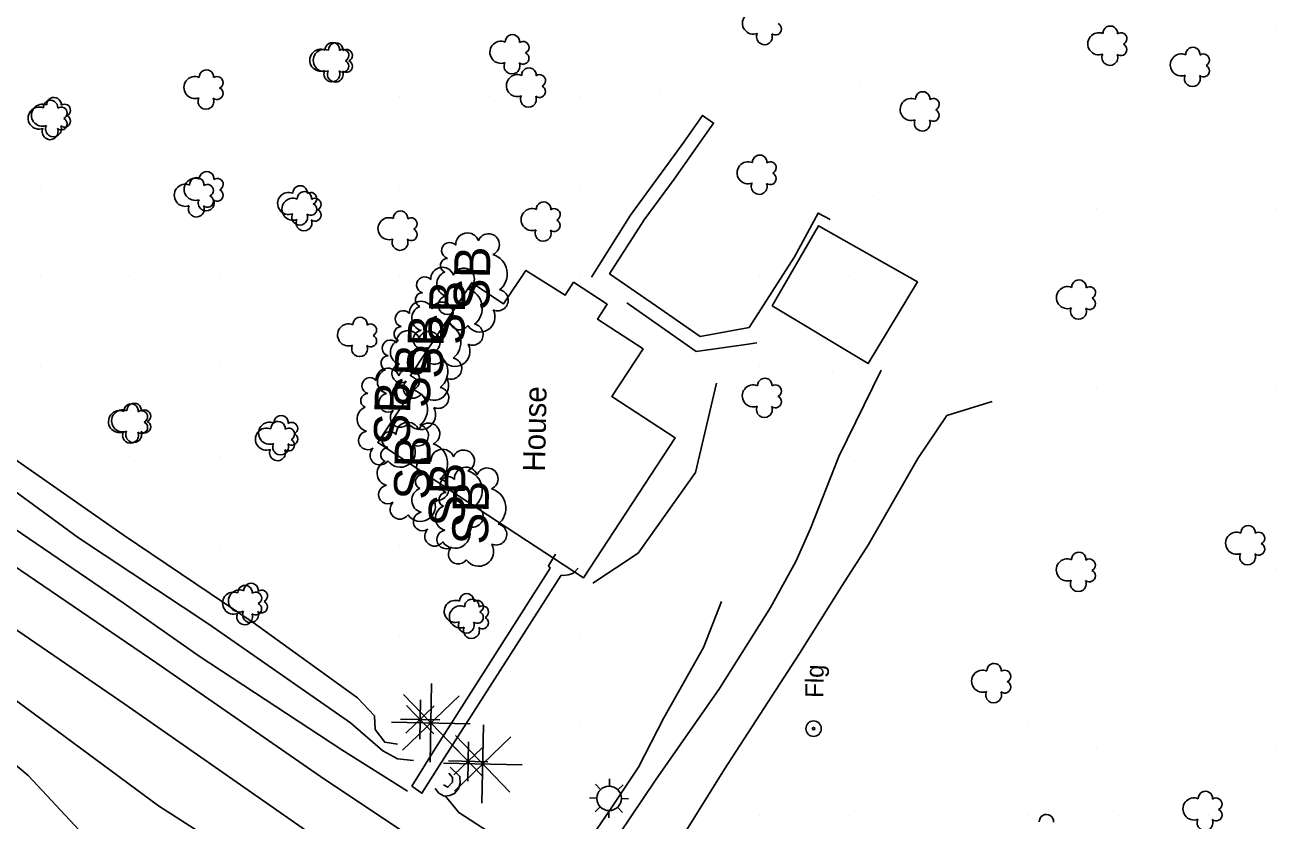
# Model space of a CAD drawing. Extents: x 19528164 to 19545171, y 7585743 to 7602745.
# Drawn here: x 19535061.7 to 19535340, y 7588133.8 to 7588310.9 of the extents above; entities that cross this region are included whole.
import ezdxf

# ---------------------------------------------------------------- set-up
doc = ezdxf.new("R2010")
doc.units = 0
for name, color, linetype in [('Default', 7, 'Continuous'), ('PhoBreakLine', 7, 'Continuous'), ('PhoBuilding', 7, 'Continuous'), ('PhoDrainageArrow', 7, 'Continuous'), ('PhoEdgeRoadPaved', 7, 'Continuous'), ('PhoEdgeSidewalk', 7, 'Continuous'), ('PhoISAEPoints', 7, 'Continuous'), ('PhoNotesDesign', 7, 'Continuous'), ('PhoVegetation', 7, 'Continuous'), ('SurAlignment', 7, 'Continuous'), ('SurEdgeEntranceUnpaved', 7, 'Continuous'), ('SurNaturalCells', 7, 'Continuous'), ('SurROWRail', 7, 'Continuous')]:
    doc.layers.add(name, color=color, linetype=linetype)

# ---------------------------------------------------------------- blocks, each defined once
blk = doc.blocks.new('SHRUB')
at = {"layer": 'Default'}
for centre, radius, start, end in [((-5.57, 5.14), 2.08, 10.5948, 214.3611), ((-0.81, 4.83), 2.81, 22.6036, 165.7836), ((3.27, 5.33), 1.59, 0.4605, 158.7839), ((6.61, 4.92), 1.8, 311.3936, 166.4114), ((-8.82, 2.41), 2.18, 45.3455, 236.8073), ((8, 0.98), 2.6, 290.9039, 94.3687), ((-8.06, -2.12), 3.34, 125.8289, 299.2848), ((8.09, -3.71), 2.42, 204.8294, 69.8871), ((-4.25, -5.95), 2.36, 157.0258, 349.7602), ((1.54, -3.45), 4.54, 220.0183, 343.6977)]:
    blk.add_arc(centre, radius, start, end, dxfattribs=at)
blk.add_text('SB', height=7.998, dxfattribs=at).set_placement((-6.62, -4.17))
blk = doc.blocks.new('TREV')
at = {"layer": 'Default'}
for p, q in [((0, -8.75), (0, 8.75)), ((-6.18, -6.19), (6.19, 6.18)), ((6.18, -6.18), (-6.18, 6.18)), ((-8.75, 0), (8.75, 0)), ((0, 0), (0, 0))]:
    blk.add_line(p, q, dxfattribs=at)
blk = doc.blocks.new('TRDC')
at = {"layer": 'PhoVegetation'}
for centre, radius, start, end in [((0.07, 3.96), 4.92, 338.2051, 201.7949), ((-5.96, -1.07), 3.52, 65.4824, 294.5175), ((4.86, -1.07), 3.21, 265.9982, 94.0018), ((-2.37, -5.89), 2.68, 142.7501, 335.3223), ((2.46, -5.82), 2.67, 206.5242, 35.4033)]:
    blk.add_arc(centre, radius, start, end, dxfattribs=at)

msp = doc.modelspace()

# ---------------------------------------------------------------- linework, layer by layer
at = {"layer": 'PhoBreakLine'}
for points in [[(19535324.95, 7587995.18), (19535295, 7588014.27), (19535258.67, 7588039.68), (19535219.66, 7588066.35), (19535185.84, 7588090.28), (19535159.88, 7588107.73), (19535126.48, 7588130.01), (19535083.85, 7588159.79), (19535046.8, 7588185.14), (19535011.18, 7588210.1), (19534967.03, 7588240.29), (19534940.46, 7588257.57), (19534928.49, 7588265.98)], [(19534985.67, 7588263.96), (19534982.83, 7588261.36), (19534981.42, 7588258.72), (19534981.19, 7588254.56), (19534982.64, 7588251.54), (19534993.07, 7588244.02), (19535010.16, 7588233.52), (19535035.49, 7588216.1), (19535057.59, 7588199.98), (19535083.47, 7588182.34), (19535100.37, 7588170.43), (19535132.13, 7588149.63), (19535146.75, 7588140.38)], [(19534986.82, 7588262.88), (19534998.99, 7588255.22), (19535016.97, 7588243.81), (19535047.5, 7588222.53), (19535083.52, 7588197.42), (19535112.43, 7588177.92), (19535135.63, 7588161.21), (19535139.45, 7588157.16), (19535139.53, 7588154.1), (19535141.69, 7588151.29), (19535141.69, 7588151.29), (19535144.57, 7588150.83)], [(19535188.01, 7588186.7), (19535198.11, 7588193.4), (19535210.84, 7588211.34), (19535215.51, 7588231.24), (19535215.51, 7588231.24)], [(19535155.11, 7588139.33), (19535158.2, 7588135.66), (19535164.68, 7588131.41), (19535170.22, 7588128.02), (19535174.93, 7588126.48), (19535178.73, 7588126.21), (19535184.36, 7588127.72), (19535188.08, 7588130.74), (19535191.65, 7588135.96), (19535198.13, 7588145.76), (19535203.79, 7588156.69), (19535212.61, 7588172.38), (19535216.59, 7588182.6)], [(19535032.29, 7588166.67), (19535046.33, 7588157.29), (19535062.39, 7588143.85), (19535074.76, 7588130.6), (19535080.78, 7588122.57), (19535094.85, 7588112.32), (19535102.21, 7588105.88), (19535125.38, 7588091.61), (19535137.29, 7588084.91)], [(19535152.88, 7588141.02), (19535153.76, 7588139.97), (19535154.91, 7588139.3), (19535156.17, 7588139.46), (19535157.24, 7588139.91), (19535158.12, 7588141.02), (19535158.49, 7588142.16), (19535158.42, 7588143.68), (19535156.29, 7588145.73)], [(19535154.74, 7588141.81), (19535155.75, 7588141.28), (19535156.78, 7588142.43), (19535156.8, 7588143.41), (19535155.98, 7588144.44)]]:
    msp.add_lwpolyline(points, dxfattribs=at)
at = {"layer": 'PhoBuilding'}
for points in [[(19535227.93, 7588248.4), (19535249.24, 7588235.56), (19535260.23, 7588253.74), (19535238.21, 7588266.25)], [(19535162.45, 7588203.27), (19535185.95, 7588187.89), (19535206.32, 7588219.03), (19535192.24, 7588228.23), (19535199.18, 7588238.85), (19535189.06, 7588245.46), (19535191.22, 7588248.79), (19535183.7, 7588253.67), (19535181.81, 7588250.79), (19535173.12, 7588256.31), (19535168.15, 7588248.89), (19535161.05, 7588253.57), (19535147.41, 7588232.9), (19535149.2, 7588231.73), (19535140.13, 7588217.99)], [(19535162.45, 7588203.27), (19535185.95, 7588187.89), (19535206.32, 7588219.03), (19535192.24, 7588228.23), (19535199.18, 7588238.85), (19535189.06, 7588245.46), (19535191.22, 7588248.79), (19535183.7, 7588253.67), (19535181.81, 7588250.79), (19535173.12, 7588256.31), (19535168.15, 7588248.89), (19535161.05, 7588253.57), (19535147.41, 7588232.9), (19535149.2, 7588231.73), (19535140.13, 7588217.99)]]:
    msp.add_lwpolyline(points, close=True, dxfattribs=at)
at = {"layer": 'PhoDrainageArrow'}
msp.add_lwpolyline([(19534985.15, 7588257.93), (19534991.63, 7588254.76), (19535003.26, 7588245.82), (19535023.92, 7588232.81), (19535050.41, 7588213.74), (19535073.55, 7588196.77), (19535102.55, 7588177.54), (19535134.09, 7588155.62), (19535141.25, 7588149.38), (19535144.56, 7588147.6), (19535148.09, 7588147.22)], dxfattribs=at)
at = {"layer": 'PhoEdgeRoadPaved'}
msp.add_lwpolyline([(19535057.27, 7588191.87), (19535090.95, 7588168.89), (19535090.97, 7588168.89), (19535127.4, 7588143.65), (19535166.06, 7588117.85), (19535239.5, 7588067.23), (19535269.12, 7588046.94), (19535311.25, 7588018.15), (19535329.73, 7588005.02), (19535324.75, 7587994.76), (19535318.21, 7587985.66), (19535298.76, 7587998.91), (19535278.77, 7588012.97), (19535253.58, 7588029.66), (19535223.79, 7588049.16), (19535206.77, 7588060.17), (19535179.37, 7588080), (19535153.78, 7588097.51), (19535135.89, 7588108.59), (19535091.35, 7588137.16), (19535042.62, 7588173.1)], dxfattribs=at)
at = {"layer": 'PhoEdgeSidewalk'}
for points in [[(19535187.68, 7588254.79), (19535196.37, 7588268.6), (19535208.24, 7588284.88), (19535212.37, 7588290.81), (19535214.85, 7588289.11), (19535206.09, 7588276.6), (19535199.44, 7588267.58), (19535191.72, 7588255.56), (19535202.13, 7588248.39), (19535211.89, 7588241.57), (19535222.75, 7588243.59), (19535232.84, 7588259.34), (19535238.13, 7588269.06), (19535240.83, 7588267.62)], [(19535195.56, 7588249.09), (19535210.98, 7588238.3), (19535222.02, 7588239.86), (19535224.5, 7588240.21)], [(19535178.53, 7588190.02), (19535178.12, 7588190.59), (19535179.67, 7588193.12)], [(19535147.69, 7588141.49), (19535152.47, 7588149.16), (19535178.53, 7588190.02)], [(19535180.92, 7588188.49), (19535181.53, 7588188.44), (19535182.49, 7588188.54), (19535183.32, 7588188.8), (19535183.78, 7588189.02), (19535184.77, 7588190.07)], [(19535147.69, 7588141.49), (19535149.95, 7588139.94), (19535153.83, 7588146.01), (19535180.92, 7588188.49)]]:
    msp.add_lwpolyline(points, dxfattribs=at)
at = {"layer": 'PhoISAEPoints'}
for p, q in [((19535081.56, 7588296.2), (19535081.56, 7588296.2)), ((19535065, 7588295), (19535065, 7588295)), ((19535105, 7588295), (19535105, 7588295)), ((19535125, 7588295), (19535125, 7588295)), ((19535145, 7588295), (19535145, 7588295)), ((19535165, 7588295), (19535165, 7588295)), ((19535065, 7588275), (19535065, 7588275)), ((19535085, 7588275), (19535085, 7588275)), ((19535105, 7588275), (19535105, 7588275)), ((19535125, 7588275), (19535125, 7588275)), ((19535145, 7588275), (19535145, 7588275)), ((19535165, 7588275), (19535165, 7588275)), ((19535165.65, 7588259.21), (19535165.65, 7588259.21)), ((19535065, 7588255), (19535065, 7588255)), ((19535085, 7588255), (19535085, 7588255)), ((19535085, 7588255), (19535085, 7588255)), ((19535105, 7588255), (19535105, 7588255)), ((19535125, 7588255), (19535125, 7588255)), ((19535145, 7588255), (19535145, 7588255)), ((19535065, 7588235), (19535065, 7588235)), ((19535085, 7588235), (19535085, 7588235)), ((19535105, 7588235), (19535105, 7588235)), ((19535125, 7588235), (19535125, 7588235)), ((19535142.55, 7588233.67), (19535142.55, 7588233.67)), ((19535076.26, 7588224.98), (19535076.26, 7588224.98)), ((19535085.12, 7588225.18), (19535085.12, 7588225.18)), ((19535085, 7588215), (19535085, 7588215)), ((19535105, 7588215), (19535105, 7588215)), ((19535125, 7588215), (19535125, 7588215)), ((19535142.12, 7588212.73), (19535142.12, 7588212.73)), ((19535105, 7588195), (19535105, 7588195)), ((19535125, 7588195), (19535125, 7588195)), ((19535145, 7588195), (19535145, 7588195)), ((19535145, 7588195), (19535145, 7588195)), ((19535165, 7588195), (19535165, 7588195)), ((19535205, 7588195), (19535205, 7588195)), ((19535154.52, 7588186.52), (19535154.52, 7588186.52)), ((19535145, 7588175), (19535145, 7588175)), ((19535185, 7588175), (19535185, 7588175)), ((19535265, 7588175), (19535265, 7588175)), ((19535185, 7588155), (19535185, 7588155)), ((19535245, 7588155), (19535245, 7588155)), ((19535265, 7588155), (19535265, 7588155)), ((19535285, 7588155), (19535285, 7588155)), ((19535305, 7588155), (19535305, 7588155)), ((19535225, 7588135), (19535225, 7588135)), ((19535245, 7588135), (19535245, 7588135)), ((19535265, 7588135), (19535265, 7588135)), ((19535285, 7588135), (19535285, 7588135)), ((19535305, 7588135), (19535305, 7588135)), ((19535325, 7588135), (19535325, 7588135))]:
    msp.add_line(p, q, dxfattribs=at)
at = {"layer": 'PhoVegetation'}
for p, q in [((19535152.72, 7588159.36), (19535146.42, 7588153.29)), ((19535152.72, 7588159.36), (19535146.42, 7588153.29)), ((19535152.61, 7588153.18), (19535146.54, 7588159.48)), ((19535152.61, 7588153.18), (19535146.54, 7588159.48)), ((19535149.49, 7588151.95), (19535149.66, 7588160.7)), ((19535149.49, 7588151.95), (19535149.66, 7588160.7)), ((19535153.95, 7588156.24), (19535145.2, 7588156.41)), ((19535153.95, 7588156.24), (19535145.2, 7588156.41)), ((19535149.57, 7588156.33), (19535149.57, 7588156.33)), ((19535149.57, 7588156.33), (19535149.57, 7588156.33)), ((19535160.15, 7588142.66), (19535160.32, 7588151.41)), ((19535163.39, 7588150.07), (19535157.08, 7588144)), ((19535163.27, 7588143.88), (19535157.2, 7588150.19)), ((19535164.61, 7588146.95), (19535155.86, 7588147.12)), ((19535160.24, 7588147.04), (19535160.24, 7588147.04))]:
    msp.add_line(p, q, dxfattribs=at)
for centre, radius, start, end in [((19535223.73, 7588311.37), 2.46, 67.0981, 290.6879), ((19535228.63, 7588310.06), 1.34, 231.6431, 64.2153), ((19535303.13, 7588309.12), 1.6, 354.8912, 182.8948), ((19535130.81, 7588305.4), 1.6, 354.8912, 182.8948), ((19535167.55, 7588304.86), 2.46, 67.0981, 290.6879), ((19535170.11, 7588307.21), 1.6, 354.8912, 182.8948), ((19535172.46, 7588305.96), 1.34, 295.4172, 124.2963), ((19535226.18, 7588308.31), 1.76, 154.3754, 23.4105), ((19535300.57, 7588306.77), 2.46, 67.0981, 290.6879), ((19535305.48, 7588307.88), 1.34, 295.4172, 124.2963), ((19535128.25, 7588303.05), 2.46, 67.0981, 290.6879), ((19535133.16, 7588304.16), 1.34, 295.4172, 124.2963), ((19535172.45, 7588303.55), 1.34, 231.6431, 64.2153), ((19535303.03, 7588303.71), 1.76, 154.3754, 23.4105), ((19535305.47, 7588305.46), 1.34, 231.6431, 64.2153), ((19535318.95, 7588302.05), 2.46, 67.0981, 290.6879), ((19535321.51, 7588304.39), 1.6, 354.8912, 182.8948), ((19535323.86, 7588303.15), 1.34, 295.4172, 124.2963), ((19535133.15, 7588301.74), 1.34, 231.6431, 64.2153), ((19535170.01, 7588301.8), 1.76, 154.3754, 23.4105), ((19535173.78, 7588299.8), 1.6, 354.8912, 182.8948), ((19535323.85, 7588300.73), 1.34, 231.6431, 64.2153), ((19535099.47, 7588297.02), 2.46, 67.0981, 290.6879), ((19535102.03, 7588299.37), 1.6, 354.8912, 182.8948), ((19535104.38, 7588298.13), 1.34, 295.4172, 124.2963), ((19535130.7, 7588299.99), 1.76, 154.3754, 23.4105), ((19535171.22, 7588297.45), 2.46, 67.0981, 290.6879), ((19535176.13, 7588298.55), 1.34, 295.4172, 124.2963), ((19535321.4, 7588298.98), 1.76, 154.3754, 23.4105), ((19535104.37, 7588295.71), 1.34, 231.6431, 64.2153), ((19535176.12, 7588296.14), 1.34, 231.6431, 64.2153), ((19535261.39, 7588294.5), 1.6, 354.8912, 182.8948), ((19535067.34, 7588292.58), 1.6, 354.8912, 182.8948), ((19535101.92, 7588293.96), 1.76, 154.3754, 23.4105), ((19535173.67, 7588294.39), 1.76, 154.3754, 23.4105), ((19535258.84, 7588292.15), 2.46, 67.0981, 290.6879), ((19535263.74, 7588293.26), 1.34, 295.4172, 124.2963), ((19535064.79, 7588290.23), 2.46, 67.0981, 290.6879), ((19535069.69, 7588288.92), 1.34, 231.6431, 64.2153), ((19535069.69, 7588291.33), 1.34, 295.4172, 124.2963), ((19535263.73, 7588290.84), 1.34, 231.6431, 64.2153), ((19535067.24, 7588287.17), 1.76, 154.3754, 23.4105), ((19535261.29, 7588289.09), 1.76, 154.3754, 23.4105), ((19535225.12, 7588280.4), 1.6, 354.8912, 182.8948), ((19535222.56, 7588278.05), 2.46, 67.0981, 290.6879), ((19535227.47, 7588279.16), 1.34, 295.4172, 124.2963), ((19535099.88, 7588275.38), 1.6, 354.8912, 182.8948), ((19535227.46, 7588276.74), 1.34, 231.6431, 64.2153), ((19535097.32, 7588273.03), 2.46, 67.0981, 290.6879), ((19535102.23, 7588274.13), 1.34, 295.4172, 124.2963), ((19535123.84, 7588272.28), 1.6, 354.8912, 182.8948), ((19535225.01, 7588274.99), 1.76, 154.3754, 23.4105), ((19535099.78, 7588269.96), 1.76, 154.3754, 23.4105), ((19535102.22, 7588271.71), 1.34, 231.6431, 64.2153), ((19535121.28, 7588269.93), 2.46, 67.0981, 290.6879), ((19535126.19, 7588271.03), 1.34, 295.4172, 124.2963), ((19535177.05, 7588269.97), 1.6, 354.8912, 182.8948), ((19535126.18, 7588268.62), 1.34, 231.6431, 64.2153), ((19535142.65, 7588265.6), 2.46, 67.0981, 290.6879), ((19535145.21, 7588267.95), 1.6, 354.8912, 182.8948), ((19535147.56, 7588266.7), 1.34, 295.4172, 124.2963), ((19535174.49, 7588267.63), 2.46, 67.0981, 290.6879), ((19535179.4, 7588268.73), 1.34, 295.4172, 124.2963), ((19535123.74, 7588266.87), 1.76, 154.3754, 23.4105), ((19535147.55, 7588264.29), 1.34, 231.6431, 64.2153), ((19535176.95, 7588264.56), 1.76, 154.3754, 23.4105), ((19535179.39, 7588266.31), 1.34, 231.6431, 64.2153), ((19535145.1, 7588262.54), 1.76, 154.3754, 23.4105), ((19535296.16, 7588252.6), 1.6, 354.8912, 182.8948), ((19535293.61, 7588250.25), 2.46, 67.0981, 290.6879), ((19535298.52, 7588251.35), 1.34, 295.4172, 124.2963), ((19535298.51, 7588248.94), 1.34, 231.6431, 64.2153), ((19535136.2, 7588244.29), 1.6, 354.8912, 182.8948), ((19535296.06, 7588247.19), 1.76, 154.3754, 23.4105), ((19535133.65, 7588241.95), 2.46, 67.0981, 290.6879), ((19535138.55, 7588243.05), 1.34, 295.4172, 124.2963), ((19535138.55, 7588240.63), 1.34, 231.6431, 64.2153), ((19535136.1, 7588238.88), 1.76, 154.3754, 23.4105), ((19535226.27, 7588230.73), 1.6, 354.8912, 182.8948), ((19535223.71, 7588228.39), 2.46, 67.0981, 290.6879), ((19535228.62, 7588229.49), 1.34, 295.4172, 124.2963), ((19535085.25, 7588225.01), 1.6, 354.8912, 182.8948), ((19535228.61, 7588227.07), 1.34, 231.6431, 64.2153), ((19535082.69, 7588222.66), 2.46, 67.0981, 290.6879), ((19535087.6, 7588223.76), 1.34, 295.4172, 124.2963), ((19535226.17, 7588225.32), 1.76, 154.3754, 23.4105), ((19535087.59, 7588221.35), 1.34, 231.6431, 64.2153), ((19535115.39, 7588218.76), 2.46, 67.0981, 290.6879), ((19535117.95, 7588221.11), 1.6, 354.8912, 182.8948), ((19535120.3, 7588219.86), 1.34, 295.4172, 124.2963), ((19535085.14, 7588219.6), 1.76, 154.3754, 23.4105), ((19535120.29, 7588217.45), 1.34, 231.6431, 64.2153), ((19535117.84, 7588215.7), 1.76, 154.3754, 23.4105), ((19535333.8, 7588197.94), 1.6, 354.8912, 182.8948), ((19535331.25, 7588195.59), 2.46, 67.0981, 290.6879), ((19535336.15, 7588194.28), 1.34, 231.6431, 64.2153), ((19535336.15, 7588196.69), 1.34, 295.4172, 124.2963), ((19535296.13, 7588191.99), 1.6, 354.8912, 182.8948), ((19535333.7, 7588192.53), 1.76, 154.3754, 23.4105), ((19535293.57, 7588189.64), 2.46, 67.0981, 290.6879), ((19535298.48, 7588190.74), 1.34, 295.4172, 124.2963), ((19535296.02, 7588186.58), 1.76, 154.3754, 23.4105), ((19535298.47, 7588188.33), 1.34, 231.6431, 64.2153), ((19535108.07, 7588182.26), 2.46, 67.0981, 290.6879), ((19535110.63, 7588184.61), 1.6, 354.8912, 182.8948), ((19535112.98, 7588183.37), 1.34, 295.4172, 124.2963), ((19535112.97, 7588180.95), 1.34, 231.6431, 64.2153), ((19535158.53, 7588179.19), 2.46, 67.0981, 290.6879), ((19535161.09, 7588181.53), 1.6, 354.8912, 182.8948), ((19535163.44, 7588180.29), 1.34, 295.4172, 124.2963), ((19535110.53, 7588179.2), 1.76, 154.3754, 23.4105), ((19535163.43, 7588177.87), 1.34, 231.6431, 64.2153), ((19535160.99, 7588176.12), 1.76, 154.3754, 23.4105), ((19535277.29, 7588167.23), 1.6, 354.8912, 182.8948), ((19535274.74, 7588164.88), 2.46, 67.0981, 290.6879), ((19535279.64, 7588165.98), 1.34, 295.4172, 124.2963), ((19535277.19, 7588161.82), 1.76, 154.3754, 23.4105), ((19535279.63, 7588163.57), 1.34, 231.6431, 64.2153), ((19535324.31, 7588138.78), 1.6, 354.8912, 182.8948), ((19535321.75, 7588136.43), 2.46, 67.0981, 290.6879), ((19535326.66, 7588137.54), 1.34, 295.4172, 124.2963), ((19535288.91, 7588133.62), 1.6, 354.8912, 182.8948), ((19535326.65, 7588135.12), 1.34, 231.6431, 64.2153), ((19535324.21, 7588133.37), 1.76, 154.3754, 23.4105)]:
    msp.add_arc(centre, radius, start, end, dxfattribs=at)
at = {"layer": 'SurAlignment'}
for radius in [1.71, 0.286]:
    msp.add_circle((19535237.12, 7588154.31), radius, dxfattribs=at)
at = {"layer": 'SurEdgeEntranceUnpaved'}
for p, q in [((19535300, 7588310), (19535300, 7588310)), ((19535300, 7588310), (19535300, 7588310)), ((19535300, 7588310), (19535300, 7588310)), ((19535340, 7588310), (19535340, 7588310)), ((19535340, 7588310), (19535340, 7588310)), ((19535340, 7588310), (19535340, 7588310)), ((19535228.38, 7588302.63), (19535228.38, 7588302.63)), ((19535203.06, 7588296.33), (19535203.06, 7588296.33)), ((19535247.64, 7588297.23), (19535247.64, 7588297.23)), ((19535185, 7588295), (19535185, 7588295)), ((19535265, 7588295), (19535265, 7588295)), ((19535185, 7588275), (19535185, 7588275)), ((19535205, 7588275), (19535205, 7588275)), ((19535223.63, 7588276.03), (19535223.63, 7588276.03)), ((19535265, 7588275), (19535265, 7588275)), ((19535250.51, 7588273), (19535250.51, 7588273)), ((19535300, 7588270), (19535300, 7588270)), ((19535300, 7588270), (19535300, 7588270)), ((19535300, 7588270), (19535300, 7588270)), ((19535340, 7588270), (19535340, 7588270)), ((19535340, 7588270), (19535340, 7588270)), ((19535340, 7588270), (19535340, 7588270)), ((19535185, 7588255), (19535185, 7588255)), ((19535205, 7588255), (19535205, 7588255)), ((19535225, 7588255), (19535225, 7588255)), ((19535245, 7588255), (19535245, 7588255)), ((19535265, 7588255), (19535265, 7588255)), ((19535225, 7588235), (19535225, 7588235)), ((19535265, 7588235), (19535265, 7588235)), ((19535241.22, 7588233.67), (19535241.22, 7588233.67)), ((19535300, 7588230), (19535300, 7588230)), ((19535300, 7588230), (19535300, 7588230)), ((19535300, 7588230), (19535300, 7588230)), ((19535340, 7588230), (19535340, 7588230)), ((19535340, 7588230), (19535340, 7588230)), ((19535340, 7588230), (19535340, 7588230)), ((19535245, 7588215), (19535245, 7588215)), ((19535265, 7588215), (19535265, 7588215)), ((19535265, 7588195), (19535265, 7588195)), ((19535300, 7588190), (19535300, 7588190)), ((19535300, 7588190), (19535300, 7588190)), ((19535300, 7588190), (19535300, 7588190)), ((19535340, 7588190), (19535340, 7588190)), ((19535340, 7588190), (19535340, 7588190)), ((19535340, 7588190), (19535340, 7588190)), ((19535300, 7588150), (19535300, 7588150)), ((19535340, 7588150), (19535340, 7588150)), ((19535340, 7588150), (19535340, 7588150)), ((19535340, 7588150), (19535340, 7588150))]:
    msp.add_line(p, q, dxfattribs=at)
at = {"layer": 'SurNaturalCells'}
for p, q in [((19535191.67, 7588141.51), (19535191.7, 7588143.14)), ((19535189.73, 7588140.75), (19535188.6, 7588141.93)), ((19535193.58, 7588140.68), (19535194.75, 7588141.81)), ((19535187.27, 7588138.88), (19535188.9, 7588138.85)), ((19535194.33, 7588138.74), (19535195.97, 7588138.71)), ((19535188.48, 7588135.78), (19535189.66, 7588136.91)), ((19535191.53, 7588134.44), (19535191.56, 7588136.07)), ((19535194.63, 7588135.66), (19535193.5, 7588136.83))]:
    msp.add_line(p, q, dxfattribs=at)
msp.add_circle((19535191.62, 7588138.79), 2.72, dxfattribs=at)
at = {"layer": 'SurROWRail'}
for points in [[(19535236.46, 7588198.87), (19535242.76, 7588214.93), (19535252.15, 7588234.13)], [(19535243.5, 7588186.15), (19535249.34, 7588195.33), (19535260.29, 7588214.43), (19535266.78, 7588224.04), (19535276.87, 7588227.17)], [(19535174.11, 7588112.3), (19535178.97, 7588113.75), (19535183.03, 7588116.78), (19535188.34, 7588122.63), (19535201.93, 7588142.82), (19535216.2, 7588163.22), (19535227.5, 7588181.3), (19535233.15, 7588191.54), (19535236.46, 7588198.87)], [(19535211.49, 7588086.54), (19535206.84, 7588093.04), (19535204.37, 7588097.98), (19535202.71, 7588103.22), (19535202.17, 7588108.45), (19535202.18, 7588112.73), (19535203.26, 7588118.05), (19535205, 7588124.15), (19535208.46, 7588131.15), (19535217.26, 7588145.29), (19535233.99, 7588171.01), (19535243.5, 7588186.15)]]:
    msp.add_lwpolyline(points, dxfattribs=at)

# ---------------------------------------------------------------- block references
at = {"layer": 'PhoVegetation', "rotation": 88.89301078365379}
for name, p, xscale, yscale in [('TRDC', (19535129.46, 7588303.02), 0.49999999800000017, 0.49999999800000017), ('TRDC', (19535067.51, 7588290.8), 0.49999999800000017, 0.49999999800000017), ('TRDC', (19535101.49, 7588274.29), 0.49999999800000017, 0.49999999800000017), ('TRDC', (19535122.3, 7588271.15), 0.49999999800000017, 0.49999999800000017), ('SHRUB', (19535160.93, 7588254.04), 0.9999999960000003, 0.9999999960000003), ('SHRUB', (19535155.36, 7588246.39), 0.9999999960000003, 0.9999999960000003), ('SHRUB', (19535150.6, 7588238.84), 0.9999999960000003, 0.9999999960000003), ('SHRUB', (19535147.71, 7588232.32), 0.9999999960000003, 0.9999999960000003), ('SHRUB', (19535143.2, 7588223.95), 0.9999999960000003, 0.9999999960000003), ('TRDC', (19535085.36, 7588222.74), 0.49999999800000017, 0.49999999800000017), ('TRDC', (19535118.06, 7588219.99), 0.49999999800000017, 0.49999999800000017), ('SHRUB', (19535147.66, 7588211.9), 0.9999999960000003, 0.9999999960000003), ('SHRUB', (19535155.38, 7588205.9), 0.9999999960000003, 0.9999999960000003), ('SHRUB', (19535160.62, 7588201.91), 0.9999999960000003, 0.9999999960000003), ('TRDC', (19535111.36, 7588182.66), 0.49999999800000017, 0.49999999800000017), ('TRDC', (19535159.37, 7588180.34), 0.49999999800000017, 0.49999999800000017), ('TREV', (19535151.94, 7588155.58), 0.9999999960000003, 0.9999999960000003), ('TREV', (19535163.49, 7588146.45), 0.9999999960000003, 0.9999999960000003)]:
    msp.add_blockref(name, p, dxfattribs=dict(at, xscale=xscale, yscale=yscale))

# ---------------------------------------------------------------- texts
at = {"layer": 'PhoNotesDesign'}
msp.add_text('House', height=4.92, rotation=88.893, dxfattribs=at).set_placement((19535177.35, 7588211.48))
at = {"layer": 'SurAlignment'}
msp.add_text('Flg', height=3.999, rotation=88.893, dxfattribs=at).set_placement((19535239.25, 7588161.13))

doc.saveas('drawing.dxf')
